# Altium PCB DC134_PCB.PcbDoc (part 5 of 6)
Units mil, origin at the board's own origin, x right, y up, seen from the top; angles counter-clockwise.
Board outline 4000 x 2750 mil, 6 copper layers (L1_Top Layer, L2_GND1, L3_Signal, L4_Plane, L5_GND2, L6_Bottom Layer), stack 57.7 mil thick; 399 components, 238 nets, 1523 pads, 671 vias.
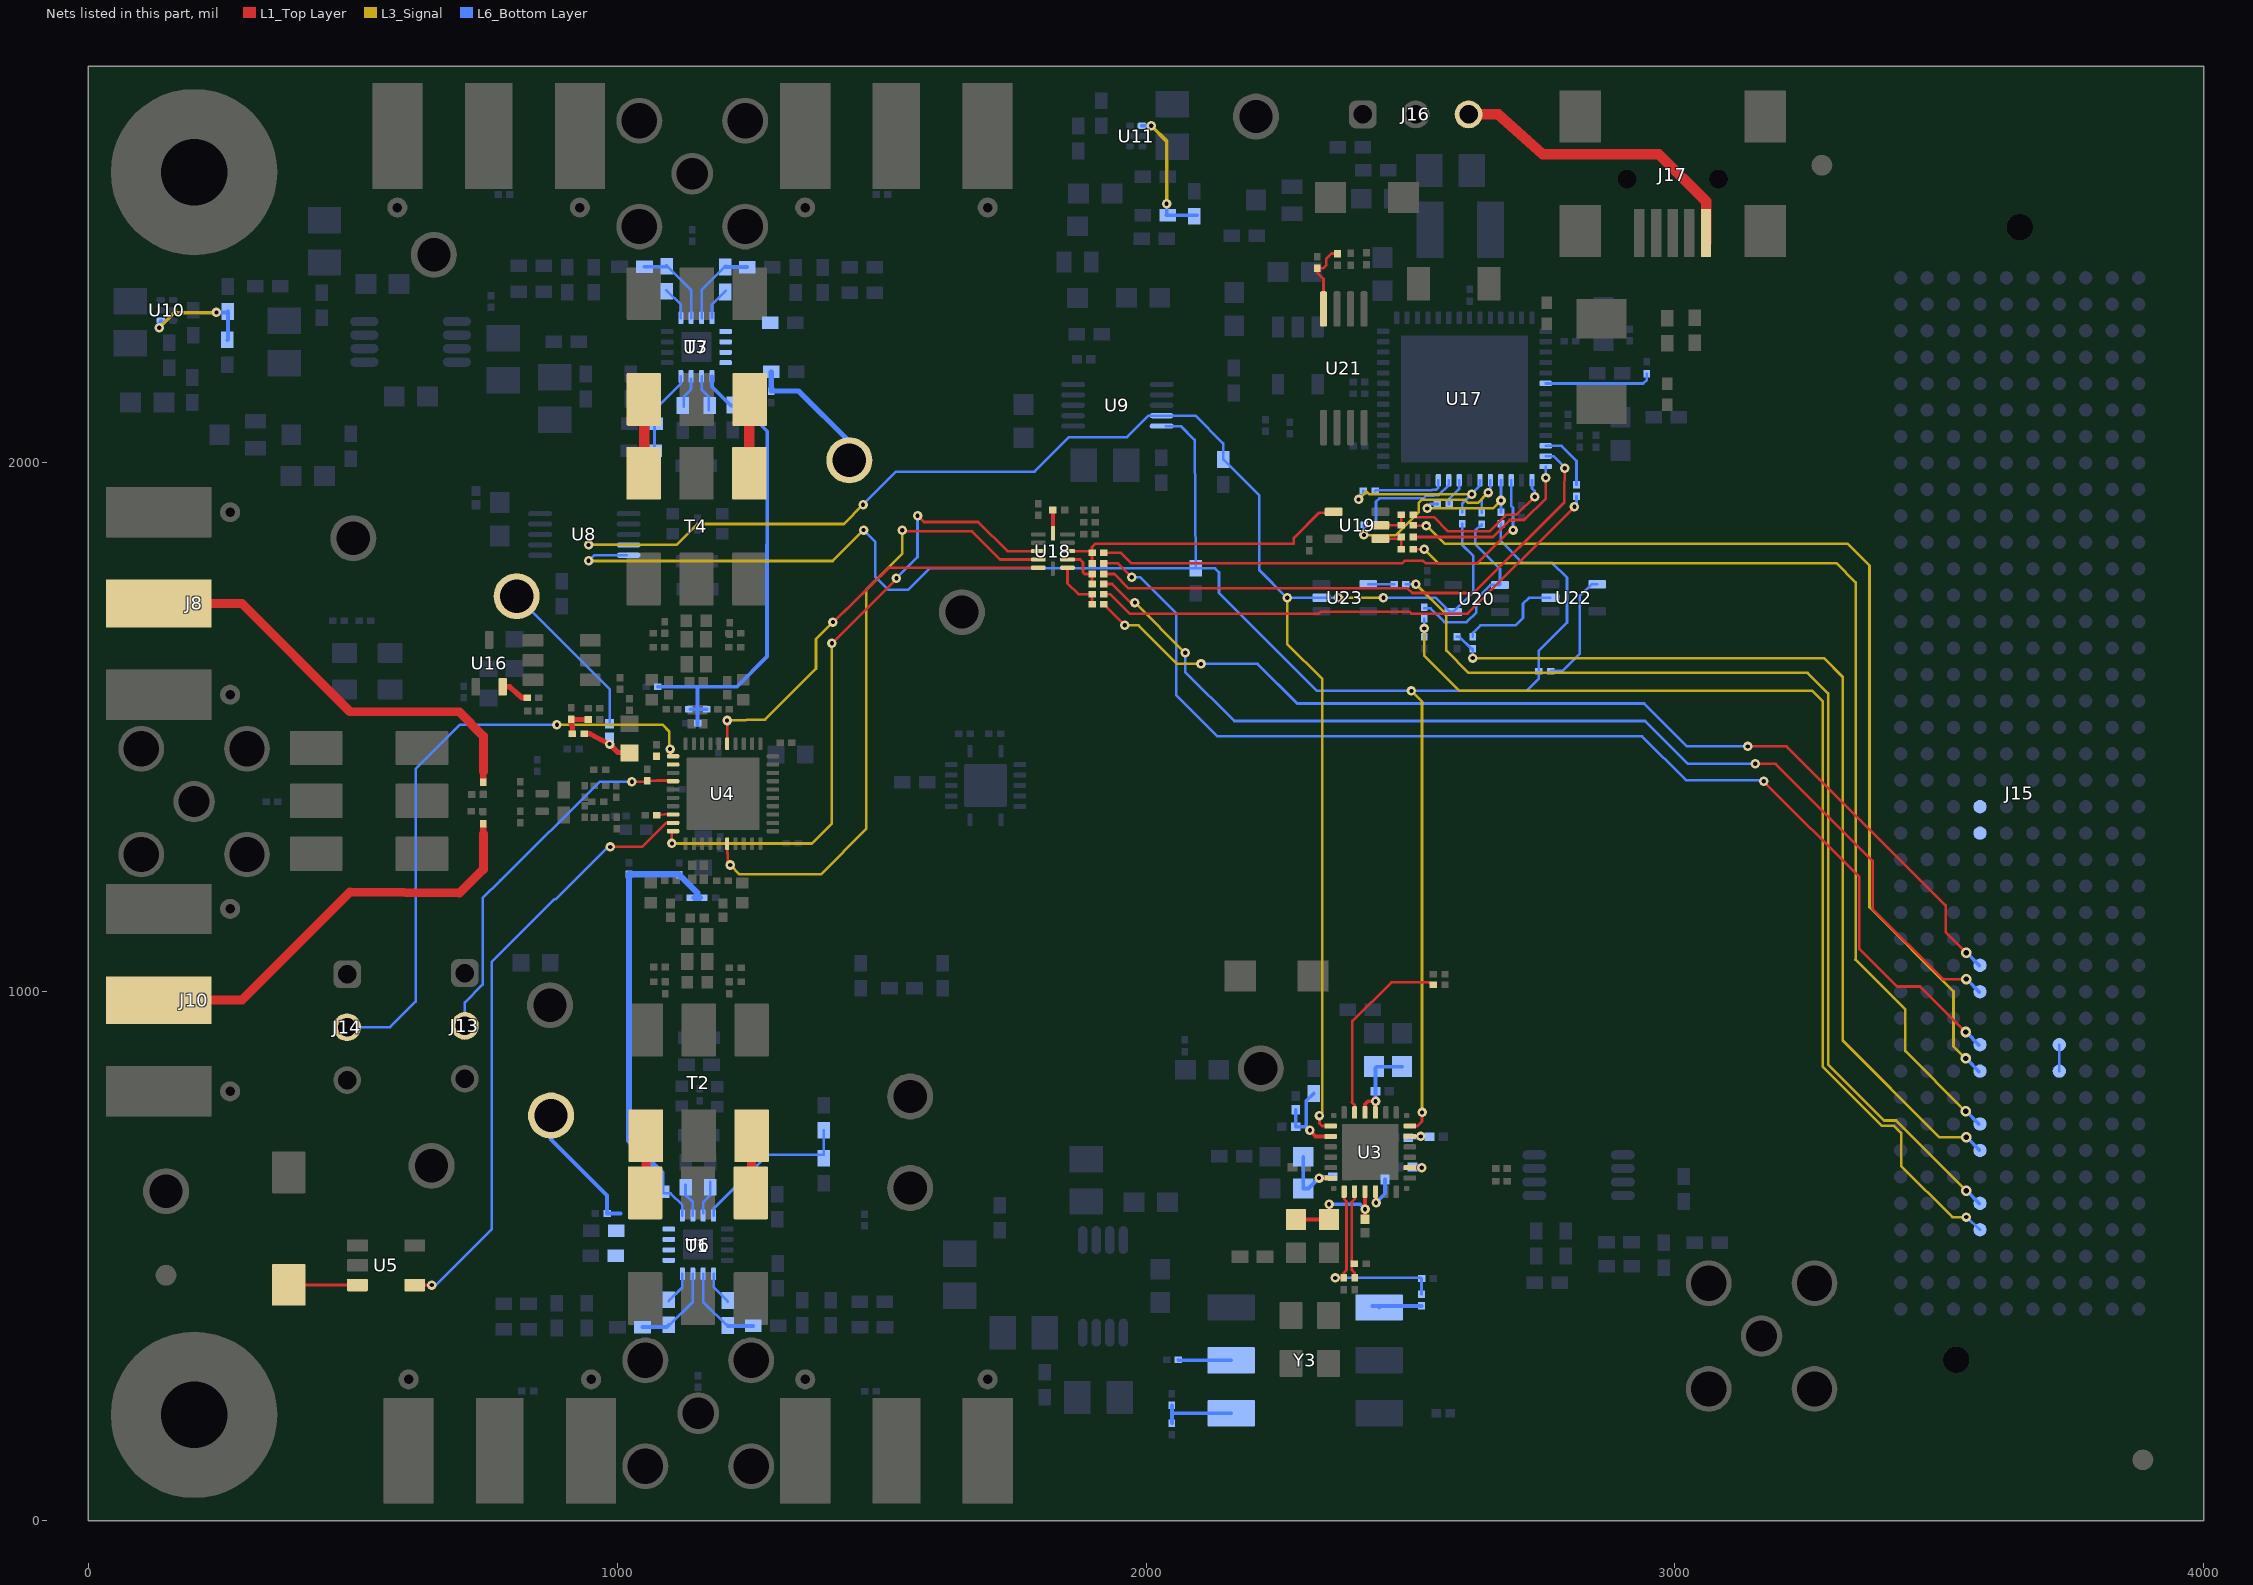
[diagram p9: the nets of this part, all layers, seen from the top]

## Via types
v1: diameter 18, hole 8, L1_Top Layer to L6_Bottom Layer, tented both sides, 429 vias
v2: diameter 20, hole 10, L1_Top Layer to L6_Bottom Layer, tented both sides, 183 vias
v3: diameter 19.68, hole 7.87, L1_Top Layer to L6_Bottom Layer, tented both sides, 37 vias
v4: diameter 19.68, hole 7.87, L1_Top Layer to L6_Bottom Layer, 17 vias
v5: diameter 18, hole 8, L1_Top Layer to L6_Bottom Layer, 5 vias

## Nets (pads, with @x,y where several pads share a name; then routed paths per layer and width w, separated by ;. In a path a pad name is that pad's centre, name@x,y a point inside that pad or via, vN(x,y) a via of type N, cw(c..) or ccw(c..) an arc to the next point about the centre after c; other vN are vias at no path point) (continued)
NetR62_1: R62.1 U3.17 | length 355.6
  L1_Top Layer w5: 2389.63,790.96 2394.47,786.11 U3.17@2394.47,771.8 ; 2390.13,790.96 2390.13,945 2464,1018 2534,1018 R62.1@2538.84,1013.66
NetR63_1: R63.1 Y3.4 | length 93.7
  L6_Bottom Layer w7: Y3.4@2428,405.98 R63.1@2520.87,405.98 ; Y3.4@2440.38,403.58 Y3.4@2440.96,403
NetR64_1: R64.1 R67.2 Y3.1 | length 146.4
  L6_Bottom Layer w7: R67.2@2049,184.02 2049,204 ; R64.1@2049,217.98 2049,204 ; Y3.1@2161.04,203 2050,203 2049,204
NetR66_1: R66.1 Y3.2 | length 100.4
  L6_Bottom Layer w7: R66.1@2061.02,304 2062.02,303 Y3.2@2161.04,303
NetR69_2: R69.2 U3.8 | length 40.6
  L1_Top Layer w7: U3.8@2498.8,667.47 v1(2521.47,667.47)
  L6_Bottom Layer w7: R69.2@2503.99,668.47 2520.47,668.47 v1(2521.47,667.47)
NetR77_1: R77.1 TP8.1 | length 313.8
  L6_Bottom Layer w5: TP8.1@810,1748 985.71,1572.29 R77.1@985.71,1506.99
NetR78_1: R78.1 R84.2 U6.2 | length 167.5
  L6_Bottom Layer w5: U6.2@1162.63,466.74 1162.63,413.81 R78.1@1209.32,367.12
  L6_Bottom Layer w7: R78.1@1209.32,369.12 1210.32,368.12 R84.2@1257.44,368.12
NetR78_2: R78.2 U6.1 | length 63.6
  L6_Bottom Layer w5: U6.1@1182.32,466.74 1182.32,441.37 R78.2@1209.32,414.37
NetR82_1: R82.1 U6.11 | length 63.8
  L6_Bottom Layer w5: 1162.63,601.74 1176.26,615.37 R82.1@1176.26,640.51 ; U6.11@1162.89,581.74 1162.89,601.12
NetR86_2: R86.2 R94.1 U6.3 | length 169
  L6_Bottom Layer w5: R94.1@1097.32,368.12 1142.95,413.75 U6.3@1142.95,466.74
  L6_Bottom Layer w7: R86.2@1047.86,366 1093.55,366 R94.1@1097.67,370.12
NetR88_1: R88.1 U6.10 | length 63.8
  L6_Bottom Layer w5: R88.1@1129.32,635.12 1129.32,615.74 1142.95,602.11 U6.10@1142.95,576.98
NetR94_2: R94.2 U6.4 | length 62.1
  L6_Bottom Layer w5: R94.2@1097.32,415.37 1123.26,441.31 U6.4@1123.26,466.74
NetR95_1: R95.1 R101.2 U7.2 | length 160.9
  L6_Bottom Layer w5: R95.1@1093.32,2373.74 1140,2327.06 U7.2@1140,2274.12
  L6_Bottom Layer w7: R101.2@1051.62,2371 1092.7,2371 R95.1@1093.32,2371.62
NetR95_2: R95.2 U7.1 | length 63.6
  L6_Bottom Layer w5: R95.2@1093.32,2326.5 1120.32,2299.5 U7.1@1120.32,2274.12
NetR99_1: R99.1 U7.11 | length 58
  L6_Bottom Layer w5: R99.1@1126,2106 1126,2125.38 ; 1126.37,2125.49 1140,2139.12 ; 1139.74,2139.74 U7.11@1139.74,2159.12
NetR103_2: R103.2 R111.1 U7.3 | length 159.5
  L6_Bottom Layer w5: U7.3@1159.69,2274.12 1159.69,2327.11 R111.1@1205.32,2372.74
  L6_Bottom Layer w7: R111.1@1204,2370.62 1204.12,2370.5 R103.2@1245.88,2370.5
NetR105_1: R105.1 U7.10 | length 69.5
  L6_Bottom Layer w5: U7.10@1159.69,2163.88 1159.69,2138.75 1173.32,2125.12 ; R105.1@1173,2100 1173,2125.13
NetR111_2: R111.2 U7.4 | length 62.1
  L6_Bottom Layer w5: U7.4@1179.37,2274.12 1179.37,2299.55 R111.2@1205.32,2325.5
NetR119_1: R119.1 R121.2 U10.1 | length 211.7
  L3_Signal w7: v1(134,2255.5) 162.5,2284 v1(242.38,2284.5)
  L6_Bottom Layer w7: v1(134,2255.5) 134,2265.28 U10.1@137.67,2268.95 ; v1(242.38,2284.5) 262.12,2284.5 R119.1@264,2286.38 264,2233.62 R121.2@263,2232.62
NetR120_1: R120.1 R122.2 U11.1 | length 257.6
  L3_Signal w7: v1(2009.81,2637.77) 2039,2608.59 v1(2039,2490.09)
  L6_Bottom Layer w7: U11.1@1992.33,2637.77 v1(2009.81,2637.77) ; v1(2039,2490.09) 2039,2468.83 2038.25,2468.09 R120.1@2041.13,2468.09 R122.2@2096.25,2468.09
NetR128_2: R128.2 R129.2 R130.1 | length 59.8
  L1_Top Layer w10: R130.1@915.48,1487.98 915.48,1502 913.5,1503.98 R129.2@913.5,1514.95 R128.2@945.48,1514.95
NetR131_1: R131.1 U16.2 | length 54.3
  L1_Top Layer w10: U16.2@783.59,1576.71 797,1576.71 819.98,1556.02 R131.1@829.98,1556.02
NetR133_2: R133.2 R139.2 U18.7 | length 103.2
  L1_Top Layer w5: U18.7@1851.56,1801.8 1851.56,1772.44 1872,1752 R139.2@1897.98,1752 R133.2@1897.98,1733
NetR134_2: R134.2 R140.2 U18.8 | length 88
  L1_Top Layer w5: U18.8@1851.56,1817.54 1875.46,1817.54 1881,1812 1881,1793 1884,1790 R140.2@1897.98,1790 R134.2@1897.98,1771
NetR135_2: R135.2 R141.2 U19.1 | length 57.9
  L1_Top Layer w5: U19.1@2443.29,1856.41 2482.39,1856.41 R135.2@2482.39,1837.59
NetR136_2: R136.2 R142.2 U19.2 | length 59.7
  L1_Top Layer w5: U19.2@2443.29,1882 R136.2@2482.98,1882 R142.2@2482.98,1902
NetR137_2: R137.2 R144.2 U18.9 U19.4 | length 569.7
  L1_Top Layer w5: U18.9@1851.56,1833.29 1894.69,1833.29 R144.2@1897.98,1830 ; R137.2@1897.98,1810 R144.2@1897.98,1830 ; U19.4@2354.71,1907.59 2352.71,1905.59 2326.67,1905.59 2279.41,1858.33 2279.41,1847 1904,1847 1897.98,1840.98 R144.2@1897.98,1830
NetR138_1: R138.1 U17.12 | length 115.2
  L6_Bottom Layer w5: U17.12@2755.56,2032.42 2785.58,2032.42 2814,2004 R138.1@2814,1959.02
NetR138_2: R138.2 R139.1 | length 1013.5
  L1_Top Layer w5: R139.1@1920.02,1752 1932,1752 1969,1715 2326.67,1715 2330.17,1718.5 2498.52,1718.5 2502.02,1715 2608,1715 v1(2810,1917)
  L6_Bottom Layer w5: v1(2810,1917) 2814,1921 R138.2@2814,1936.98
NetR140_1: R140.1 U17.13 | length 1067.7
  L1_Top Layer w5: R140.1@1920.02,1790 1940,1790 1967,1763 2494.67,1763 2503.55,1754.11 2619.45,1754.11 2791,1925.67 2791,1942 v1(2792,1990)
  L6_Bottom Layer w5: U17.13@2755.56,2012.73 2770.27,2012.73 2792,1991 v1(2792,1990)
NetR141_1: R141.1 U17.14 | length 341.2
  L1_Top Layer w5: R141.1@2505.02,1860 2656,1860 2688,1892 2693.67,1892 ; 2693.76,1892 2715,1892 2756,1933 v1(2756,1972)
  L6_Bottom Layer w5: U17.14@2755.56,1993.05 2755.56,1986.44 v1(2756,1972)
NetR142_1: R142.1 U17.15 | length 303.4
  L1_Top Layer w5: R142.1@2505.02,1902 2509.52,1897.5 2544.5,1897.5 2571.46,1870.54 2649.57,1870.54 2681.02,1902 2700,1902 v1(2735,1936)
  L6_Bottom Layer w5: U17.15@2730,1967.43 2730,1952 2735,1947 v1(2735,1936)
NetR143_1: R143.1 U17.22 | length 53.8
  L6_Bottom Layer w5: R143.1@2573.02,1921.57 2573.02,1931.53 2592.18,1950.69 U17.22@2592.18,1967.46
NetR143_2: R143.2 R156.1 U17.18 | length 245.4
  L3_Signal w5: v1(2532,1914) 2656.29,1914 v1(2671.29,1929)
  L6_Bottom Layer w5: v1(2532,1914) 2532,1917 v1@2536.57,1921.57 ; R143.2@2550.97,1921.57 v1@2536.57,1921.57 ; R143.2@2551.66,1922.34 2537.34,1922.34 v1@2536.57,1921.57 ; U17.18@2670.92,1967.46 2671.29,1967.08 R156.1@2671.29,1907.02
NetR144_1: R144.1 U17.17 | length 909.8
  L1_Top Layer w5: R144.1@1920.02,1830 1953,1830 1973,1810 2484,1810 2489,1815 2524,1815 2529,1810 2626,1810 2690.78,1874.78 2692.56,1873 v1(2694,1873)
  L6_Bottom Layer w5: U17.17@2690.6,1967.46 2690.6,1919 2694,1915.6 v1(2694,1873)
NetR146_1: R146.1 U17.23 | length 203.5
  L6_Bottom Layer w5: R146.1@2435.02,1883 2435.02,1927 2441.22,1933.2 2524.87,1933.2 2529.81,1938.15 2544.14,1938.15 2545.49,1939.5 2553.5,1939.5 2572.49,1958.49 U17.23@2572.49,1967.46
NetR146_2: R146.2 R157.1 U17.19 | length 372.2
  L3_Signal w5: v1(2412,1864) 2412,1863 2472,1863 2515.5,1906.5 2515.5,1923.83 2522.17,1930.5 2603.17,1930.5 2609.17,1924.5 2627.5,1924.5 v1(2647,1944)
  L6_Bottom Layer w5: v1(2412,1864) 2412,1882.02 R146.2@2412.98,1883 ; R157.1@2635,1906.02 2635,1932 v1(2647,1944) 2651.23,1948.23 U17.19@2651.23,1967.46
NetR147_1: R147.1 U18.12 | length 44.2
  L1_Top Layer w7: U18.12@1824,1866.76 R147.1@1823.98,1911
NetR149_1: R149.1 U17.24 | length 136.5
  L6_Bottom Layer w5: R149.1@2433.02,1947 2434.17,1948.15 2539.99,1948.15 2541.35,1949.5 2548.84,1949.5 2552.8,1953.46 U17.24@2552.8,1967.46
NetR149_2: R149.2 R161.1 U17.20 | length 316.3
  L3_Signal w5: v1(2402,1931) 2417,1946 2422,1941 v1(2616,1941)
  L6_Bottom Layer w5: v1(2402,1931) 2410.98,1939.98 R149.2@2410.98,1947 ; R161.1@2598,1907.02 2598,1923.55 2631.55,1957.09 U17.20@2631.55,1967.46
NetR152_2: R152.2 U17.6 | length 206.6
  L6_Bottom Layer w5: U17.6@2755.56,2150.53 2755.56,2150.19 2940.17,2150.19 2947,2157.02 R152.2@2947,2168.98
NetR157_2: R157.2 R167.2 U20.1 | length 339
  L6_Bottom Layer w5: R167.2@2526,1725.02 2537.98,1725.02 2564,1699 2606.08,1699 2624.5,1717.42 2624.5,1742.5 2651.21,1769.21 U20.1@2669.4,1769.21 2669.4,1799.6 2622.5,1846.5 2622.5,1871.83 2632.17,1881.5 2635,1881.5 R157.2@2635,1883.98
NetR160_1: R160.1 R162.1 U21.4 | length 138.5
  L1_Top Layer w5: U21.4@2335.61,2291.2 2335.61,2348 2324,2359.61 R160.1@2324,2367.98 2334.98,2367.98 2340.59,2373.59 2340.59,2386 2350.64,2396.05 R162.1@2362,2396.02
NetR165_2: R165.2 U22.2 | length 197.6
  L6_Bottom Layer w5: R165.2@2618,1671.02 2618,1678.65 2632.35,1693 2699,1693 2713,1707 2713,1734 2724,1745 U22.2@2764.71,1745
NetR166_1: R166.1 U22.4 | length 220.3
  L6_Bottom Layer w5: R166.1@2765.02,1606 2766.02,1607 2788,1607 2820,1639 2820,1748 2842.59,1770.59 U22.4@2853.29,1770.59
NetR168_2: R168.2 U23.4 | length 48.7
  L6_Bottom Layer w5: U23.4@2420.29,1770.61 R168.2@2468.98,1770.61
NetS1_2: S1.2 U5.3 | length 129.6
  L1_Top Layer w5: S1.2@379.25,445.45 U5.3@508.87,445.45
NetT1_4: T1.4 T2.6 | length 122
  L1_Top Layer w17: T1.4@1254.24,605.74 T2.6@1254.24,727.74
NetT1_6: T1.6 T2.4 | length 122
  L1_Top Layer w17: T1.6@1054.24,605.74 T2.4@1054.24,727.74
NetT3_4: T3.4 T4.6 | length 110
  L1_Top Layer w20: T4.6@1051,1984 T3.4@1051,2094
NetT3_6: T3.6 T4.4 | length 110
  L1_Top Layer w20: T4.4@1249.98,1983 T3.6@1249.98,2093
OE: R70.1 R72.2 U3.11 | length 45.2
  L1_Top Layer w7: U3.11@2498.8,726.53 v1(2519.47,726.53)
  L6_Bottom Layer w7: R72.2@2495.99,724 2516.94,724 v1(2519.47,726.53)
PD_AMP_CHA: R83.1 R87.2 U6.12 | length 309.3
  L6_Bottom Layer w5: U6.12@1182.32,576.98 1182.32,589.74 1283.87,691.74 1390.25,691.74 1390.87,692.37 R87.2@1390.87,737.74
PD_AMP_CHB: R100.1 R104.2 U7.12 | length 160.2
  L6_Bottom Layer w5: R100.1@1070.52,2024 R104.2@1070.52,2074 1071,2074.48 1071,2100 1120.32,2150.32 U7.12@1120.32,2163.88
PDN_SYNC: J14.2 U4.1 | length 1157.3
  L1_Top Layer w5: U4.1@1100,1444.72 v1(1100,1459)
  L3_Signal w5: v1(886,1505) 1086,1505 1098.5,1492.5 1098.5,1460.5 v1(1100,1459)
  L6_Bottom Layer w5: J14.2@489.5,933 570.5,933 619,981.5 619,1421.5 702.5,1505 v1(886,1505)
PDN_SYNC_FPGA: J15.G21
REFBUF: C46.1 J13.2 U4.4 | length 707.7
  L1_Top Layer w5: v1(1028,1397) 1055.02,1397 C46.1@1057,1398.98 1075.14,1398.98 1075.67,1399.5 1104.63,1399.5 U4.4@1105.51,1398.62 ; U4.4@1103.54,1398.62 U4.4@1103.54,1398.84
  L6_Bottom Layer w5: J13.2@712,935.5 712,980.08 745.75,1013.83 745.75,1177.28 779.24,1210.77 967,1397 v1(1028,1397)
REFSEL: R61.2 U3.4 | length 72.1
  L1_Top Layer w7: U3.4@2433.84,622.2 2435,621.04 v1(2435,601.3)
  L6_Bottom Layer w7: v1(2435,601.3) 2452,618.3 R61.2@2452,645.01
RESET: U4.9 U5.4 | length 1147
  L1_Top Layer w5: U5.4@617.13,445.45 v1(649.55,445.45) ; v1(987,1274) 1047,1274 1092.88,1319.88 U4.9@1105.51,1319.88
  L6_Bottom Layer w5: v1(649.55,445.45) 657.45,445.45 763,551 763,1057 881.17,1175.17 884.17,1175.17 983,1274 v1(987,1274)
RESET_FPGA: J15.G22
SCL_I2C: R154.1 R156.2 R166.2 U3.12 U8.5 U9.5 | length 3684.4
  L1_Top Layer w5: U3.12@2498.8,746.21 2513.21,746.21 2522,755 v1(2522,772)
  L3_Signal w5: v1@946.41,1814.59 1407.59,1814.59 v1(1466,1873) ; v1(2502,1569) 2522,1549 v1(2522,772)
  L6_Bottom Layer w5: v1(946,1815) 956.71,1825.71 U8.5@1017.66,1825.71 ; v1(1466,1873) 1488,1851 1488,1785 1513,1760 1550,1760 1590.62,1800.62 R154.1@2094,1800.62 ; U9.5@2037.16,2069.63 2065.7,2069.63 2091.91,2043.42 2091.91,2040 R154.1@2094,1800.62 ; R156.2@2671.29,1884.98 2670.92,1884.6 2670.92,1852 2711.92,1811 2768,1811 2796,1783 2796,1698 2742.98,1644.98 2742.98,1592.6 2719.38,1569 v1(2502,1569) 2323,1569 2138,1754 2138,1793 2130.38,1800.62 R154.1@2094,1800.62
SCL_I2C_FPGA: J15.G34 R163.2 R165.1 | length 1802.9
  L3_Signal w5: v1(2618,1631) 3282,1631 3317.5,1595.5 3317.5,907.5 3499.85,725.15 v2(3551,725.15)
  L6_Bottom Layer w5: R163.2@2588,1671.02 2592.98,1671.02 2615.02,1648.98 R165.1@2618,1648.98 v1(2618,1631)
  L6_Bottom Layer w6.6: v2@3552,725.15 J15.G34@3576,700.3
SCLK: U4.35 U18.5 | length 785.1
  L1_Top Layer w5: U4.35@1207.87,1469.49 v1@1207.87,1515 ; v1(1408,1699) v1@1408.89,1699 ; v1@1409,1699 v1@1408.89,1699 ; U18.5@1796.44,1801.8 1514.2,1801.8 1408.94,1699.06 v1@1408.89,1699
  L3_Signal w5: v1(1207.87,1513) 1280,1515 1376,1611 1376,1667 v1(1408,1699)
SCLK_FPGA: J15.G27 R133.1 | length 1967.9
  L1_Top Layer w5: R133.1@1920.02,1733 v1(1960.02,1693) ; v1(3138,1464) 3211.18,1464 3512,1163.18 3512,1113 v2(3551,1074)
  L3_Signal w5: v1(1960.02,1693) 1986,1693 2059,1620 v1(2104,1620)
  L6_Bottom Layer w5: v1(2104,1620) 2211,1620 2286,1545 2942,1545 3023,1464 v1(3138,1464)
  L6_Bottom Layer w6.6: v2@3552,1074 J15.G27@3576,1049.15
SDA_I2C: R155.1 R161.2 U3.19 U8.4 U9.4 U20.4 U23.2 | length 3300.6
  L1_Top Layer w5: v1(2328,766) 2328,751 2332.79,746.21 U3.19@2349.2,746.21
  L3_Signal w5: v1(946,1845) 1112,1845 1151.5,1884.5 1428.5,1884.5 v1(1465,1921) ; v1(2267,1745.02) 2267,1658 2333.5,1591.5 2333.5,771.5 v1(2328,766) ; v1(2363.98,1745.02) v1(2449.02,1745.02)
  L6_Bottom Layer w5: v1(946,1845) 946.39,1845.39 U8.4@1017.66,1845.39 ; v1(1465,1921) 1527.39,1983.39 1789.39,1983.39 1854.75,2048.75 1964.25,2048.75 2004.82,2089.31 2037.16,2089.31 2093.69,2089.31 2146,2037 R155.1@2146,2007 ; R155.1@2146,2006.62 R155.1@2146,2007 ; v1(2363.98,1745.02) U23.2@2331.71,1745.02 v1(2267,1745.02) 2214,1798.02 2214,1939 R155.1@2146,2007 ; v1(2449.02,1745.02) 2547.93,1745.02 2574.92,1718.03 U20.4@2580.82,1718.03 2619,1756.21 2619,1824 2598,1845 R161.2@2598,1884.98
SDA_IN_I2C_FPGA: J15.G36 R168.1 | length 2020.4
  L3_Signal w5: v1(2510.39,1770.61) 2568,1713 2568,1645 2610,1603 3251,1603 3290,1564 3290,862.25 3395.75,756.5 3418.5,756.5 v2(3551,624)
  L6_Bottom Layer w5: R168.1@2491.02,1770.61 v1(2510.39,1770.61)
  L6_Bottom Layer w6.6: v2@3552,624 J15.G36@3576,599.15
SDA_OUT_I2C_FPGA: J15.G37 R164.2 R167.1 | length 2026.3
  L3_Signal w5: v1(2526,1687) 2526,1636 2593,1569 3260,1569 3280,1549 3280,858.11 3391.61,746.5 3414.36,746.5 3428,732.86 3428,671 3525,574 v1(3551,574)
  L6_Bottom Layer w5: R164.2@2526,1671.02 v1(2526,1687) R167.1@2526,1705.09 ; v1(3551,574) J15.G37@3577,550
SDIO: U4.10 U18.3 | length 1247.9
  L1_Top Layer w5: v1(1103.54,1280.46) 1103.54,1302.17 U4.10@1105.51,1304.13 ; v1(1406,1659) 1528,1781 v1(1528,1782) ; v1(1568,1900.15) 1579.85,1888.29 1682.71,1888.29 1737.71,1833.29 U18.3@1796.44,1833.29
  L3_Signal w5: v1(1103.54,1280.46) 1368.46,1280.46 1406,1318 v1(1406,1659)
  L6_Bottom Layer w5: v1(1528,1782) 1568,1822 v1(1568,1900.15)
SDIO_I_FPGA: J15.G31 R136.1 | length 1936.4
  L1_Top Layer w5: R136.1@2505.02,1882 2506.02,1881 v1(2530,1881)
  L3_Signal w5: v1(2530,1881) 2531,1881 2565.04,1846.96 3071.93,1846.96 3071.97,1847 3327,1847 3368,1806 3368,1160 3527,1001 3527,897 v2(3550,874)
  L6_Bottom Layer w6.6: v2@3551,874 J15.G31@3575,849.15
SDIO_O_FPGA: J15.G30 R137.1 | length 2203.2
  L1_Top Layer w5: R137.1@1920.02,1810 1946.98,1810 v1(1972.98,1784) ; v1(3168,1398) 3349,1217 3349,1081 3420,1010 3464,1010 v2(3550,924)
  L6_Bottom Layer w5: v1(1972.98,1784) 1989,1784 2057,1716 2057,1561 2135,1483 2938,1483 3020.85,1400.15 3168,1400.15 v1(3168,1398)
  L6_Bottom Layer w6.6: v2@3551,924 J15.G30@3575,899.15
SDIO_OE_FPGA: J15.G33 R135.1 | length 1984.1
  L1_Top Layer w5: R135.1@2505.02,1837 v1(2526,1837)
  L3_Signal w5: v1(2526,1837) 2552.34,1810.66 3305.34,1810.66 3342,1774 3342,1061 3341.66,1060.66 3436,966.31 3436,888 v2(3550,774)
  L6_Bottom Layer w6.6: v2@3551,774 J15.G33@3575,749.15
SECREF_N: R59.1 R68.1 U3.2 | length 167.5
  L1_Top Layer w5: R59.1@2394.47,459.02 2394.47,468.61 2389.24,473.85 2389.24,602.65 2394.47,607.89 U3.2@2394.47,622.2
SECREF_P: R55.1 R63.2 R65.2 U3.1 | length 376.8
  L1_Top Layer w5: v1(2357.65,459.02) R55.1@2374,459.02 2374,468.61 2379.24,473.85 2379.24,603.44 2374.79,607.89 U3.1@2374.79,622.2
  L6_Bottom Layer w5: v1(2357.65,459.02) 2519.25,459.02 2520.87,457.4 R63.2@2520.87,428.02
SEN: U4.16 U18.4 | length 1215.6
  L1_Top Layer w5: U4.16@1207.99,1280.06 1207.99,1262.46 1209.06,1261.39 1209.06,1244.7 v1(1214,1239.76) ; v1(1539,1872.54) 1541,1870.54 1671,1870.54 1724,1817.54 U18.4@1796.44,1817.54
  L3_Signal w5: v1(1214,1239.76) 1231.7,1222.06 1385.06,1222.06 1471,1308 1471,1760 1539,1828 v1(1539,1872.54)
SEN_FPGA: J15.G28 R134.1 | length 2049
  L1_Top Layer w5: R134.1@1920.02,1771 1936,1771 1971,1736 v1(1979,1736) ; v1(3152,1431) 3190.41,1431 3374,1247.41 3374,1157 3507,1024 v2(3551,1024)
  L3_Signal w5: v1(1979,1736) v1(2074,1641)
  L6_Bottom Layer w5: v1(2074,1641) 2074,1605 2167,1512 2944,1512 3025,1431 v1(3152,1431)
  L6_Bottom Layer w6.6: v2@3552,1024 J15.G28@3576,999.15
SMA_CLK_N: J10.1 R49.1 | length 833.3
  L1_Top Layer w12: 747.02,1298.18 R49.1@747.02,1318.94
  L1_Top Layer w17: J10.1@105,984.25 J10.1@133,984.25 290.36,984.25 494.61,1188.5 702,1187.15 747.02,1232.18 ; 747.02,1230.9 747.02,1232.18 ; 747.02,1298.18 747.02,1232.18
SMA_CLK_P: J8.1 R43.1 | length 833.3
  L1_Top Layer w12: R43.1@747.02,1395.59 747.02,1416.35
  L1_Top Layer w17: J8.1@105,1734.25 J8.1@133,1734.25 290.36,1734.25 494.61,1530 702,1528.65 747.02,1483.63 747.02,1416.35
STATUS: R54.1 R57.2 R58.2 U3.20 | length 164.8
  L1_Top Layer w7: v1(2310,738) 2320.47,726.53 U3.20@2349.2,726.53
  L6_Bottom Layer w7: R54.1@2283,777.01 R57.2@2282.99,745 2303,745 2303,793.76 R58.2@2317,807.76
TDI_TDO: J15.D30 J15.D31 | length 50
  L6_Bottom Layer w5: J15.D31@3727,850 J15.D30@3727,900
USB_+5Vin: J16.3 J17.1 | length 592.8
  L1_Top Layer w20: J16.3@2610,2659 2666,2659 2750,2584 2969.91,2584 3058.99,2494.91 J17.1@3058.99,2434.64 J17.1@3058.99,2416.64
VCM: R73.2 U4.8 | length 26.7
  L1_Top Layer w5: R73.2@1076.87,1333.62 1089.75,1335.5 U4.8@1103.41,1335.5
VCM_FDA_CHA: C5.2 C51.2 R7.1 R8.2 R74.2 U6.9 | length 856.5
  L6_Bottom Layer w5: C51.2@1084.49,622.9 1089.31,618.74 1101.32,618.74 1123.26,596.8 U6.9@1123.26,576.98
  L6_Bottom Layer w12: C51.2@1083.49,621.74 1083.49,658 1022.5,718.99 R74.2@1022.5,1221.98 1116.78,1221.98 C5.2@1117.28,1221.48 1151.42,1187.33 1151.42,1178.08 ; 1146.8,1178.08 1156.05,1178.08
VCM_FDA_CHB: C13.2 C56.2 R21.1 R22.2 R75.2 U7.9 | length 910.8
  L6_Bottom Layer w7: R75.2@1077.02,1576.98 1147.5,1576.98 1226.48,1576.98 1283.5,1634 1284,2060 1234.38,2109.62 1228.76,2109.62 1229.76,2108.62 1214.81,2108.62 1179.37,2144.06 U7.9@1179.37,2163.88 ; R21.1@1138.82,1534.5 1150.5,1534.5 ; C13.2@1152,1504.52 1152,1572.48 ; 1156,1534.5 R22.2@1169.02,1534.5
VDD_REF: C28.1 C29.1 L8.2 U3.3 | length 215.2
  L1_Top Layer w7: L8.2@2283.89,569.5 C28.1@2346.26,569.5 v1(2346.26,598.26) ; C29.1@2414.16,569.99 v1(2414.16,588.68) U3.3@2414.16,622.2
  L6_Bottom Layer w7: v1(2346.26,598.26) 2404.57,598.26 v1(2414.16,588.68)
VDD_VCO: C32.1 C33.1 L9.2 U3.24 | length 147.2
  L1_Top Layer w7: v1(2327.21,647.79) U3.24@2349.2,647.79
  L6_Bottom Layer w7: L9.2@2297.44,688 C32.1@2297.44,628 2307.43,628 v1(2327.21,647.79) 2329.57,650.15 C33.1@2353.51,650.15
VDDO_12: C35.1 C36.1 L10.2 U3.15 U3.16 | length 173.1
  L1_Top Layer w7: U3.16@2414.16,771.8 2414.16,787.16 2420.01,793.01 v1(2434.01,793.01) 2434.01,771.97 U3.15@2433.84,771.8
  L6_Bottom Layer w7: v1(2434.01,793.01) C36.1@2434.01,811.75 2434.01,855.7 2436.81,858.5 C35.1@2484.32,858.5
VREF: C44.1 C45.1 R77.2 R130.2 U4.2 | length 98.9
  L1_Top Layer w10: R130.2@937.52,1487.98 948.02,1487.98 v1(985.71,1468.29) 1001.56,1452.44 C44.1@1025,1452.44
VS+_CHA: C66.1 C67.1 R91.1 TP9.1 U6.5 U6.6 U6.7 U6.8 | length 255.1
  L6_Bottom Layer w7: TP9.1@875,766 875,720.61 980.89,614.72 R91.1@980.89,580.74 1006.87,580.74
VS+_CHB: C64.1 C65.1 R106.1 TP11.1 U7.5 U7.6 U7.7 U7.8 | length 223.3
  L6_Bottom Layer w10: R106.1@1291.38,2136.02 1342.98,2136.02 TP11.1@1439,2040 ; R106.1@1291.38,2136.14 C65.1@1291.38,2172
pads on no net: FID1.1 FID2.1 FID3.1 H1.1 H2.1 H3.0 H4.0 J15.A2 J15.A3 J15.A6 J15.A7 J15.A10 J15.A11 J15.A14 J15.A15 J15.A18 J15.A19 J15.A22 J15.A23 J15.A26 J15.A27 J15.A30 J15.A31 J15.A34 J15.A35 J15.A38 J15.A39 J15.B1 J15.B4 J15.B5 J15.B8 J15.B9 J15.B12 J15.B13 J15.B16 J15.B17 J15.B20 J15.B21 J15.B24 J15.B25 J15.B28 J15.B29 J15.B32 J15.B33 J15.B36 J15.B37 J15.B40 J15.C2 J15.C3 J15.C6 J15.C7 J15.C10 J15.C11 J15.C14 J15.C15 J15.C18 J15.C19 J15.C22 J15.C23 J15.C26 J15.C27 J15.C30 J15.C31 J15.C34 J15.C35 J15.C37 J15.C39 J15.D1 J15.D4 J15.D5 J15.D8 J15.D9 J15.D11 J15.D12 J15.D14 J15.D15 J15.D17 J15.D18 J15.D20 J15.D21 J15.D23 J15.D24 J15.D26 J15.D27 J15.D29 J15.D32 J15.D33 J15.D34 J15.D35 J15.D36 J15.D38 J15.D40 J15.E18 J15.E19 J15.E21 J15.E22 J15.E24 J15.E25 J15.E27 J15.E28 J15.E30 J15.E31 J15.E33 J15.E34 J15.E36 J15.E37 J15.E39 J15.F1 J15.F7 J15.F8 J15.F10 J15.F11 J15.F13 J15.F14 J15.F16 J15.F17 J15.F19 J15.F20 J15.F22 J15.F23 J15.F25 J15.F26 J15.F28 J15.F29 J15.F31 J15.F32 J15.F34 J15.F35 J15.F37 J15.F38 J15.F40 J15.G2 J15.G3 J15.G7 J15.G9 J15.G10 J15.G12 J15.G13 J15.G15 J15.G16 J15.G18 J15.G19 J15.G24 J15.G25 J15.H1 J15.H5 J15.H7 J15.H8 J15.H10 J15.H11 J15.H13 J15.H14 J15.H16 J15.H17 J15.H19 J15.H20 J15.H22 J15.H23 J15.H25 J15.H26 J15.H28 J15.H29 J15.H31 J15.H32 J15.H34 J15.H35 J15.H37 J15.H38 J15.H40 J15.J2 J15.J3 J15.J6 J15.J7 J15.J9 J15.J10 J15.J12 J15.J13 J15.J15 J15.J16 J15.J18 J15.J19 J15.J21 J15.J22 J15.J24 J15.J25 J15.J27 J15.J28 J15.J30 J15.J31 J15.J33 J15.J34 J15.J36 J15.J37 J15.J39 J15.K1 J15.K4 J15.K5 J15.K7 J15.K8 J15.K10 J15.K11 J15.K13 J15.K14 J15.K19 J15.K20 J15.K22 J15.K23 J15.K25 J15.K26 J15.K28 J15.K29 J15.K31 J15.K32 J15.K34 J15.K35 J15.K37 J15.K38 J15.K40 J15.MH1 J15.MH2 J17.4 J17.10 J17.11 LBL1.0 T1.2 T2.2 T3.2 T4.2 T5.2 U1.1 U1.4 U2.6 U3.7 U3.9 U3.10 U3.13 U3.14 U3.A1 U3.A2 U3.A3 U3.A4 U4.27 U6.17@1152.79,521.86 U7.17@1149.84,2219 U8.3 U9.3 U14.4 U17. U17.25 U17.26 U17.27 U17.28 U17.29 U17.30 U17.32 U17.33 U17.34 U17.35 U17.37 U17.38 U17.39 U17.40 U17.42 U17.46 U17.47 U17.48 U17.49 U17.51 U17.52 U17.53 U17.54 U18.2 U18.10 U21.6 U21.7 Y3.5
copper on no net: | length 106.6
  L1_Top Layer w5: 419,1357 v1(484,1357)
  L4_Plane w4.4: 3403,1575 3403,1582
  L6_Bottom Layer w6.6: v2@3553,2074.26 3576.7,2049.71 3577,2049.4
  other v2: 3552,2074.26

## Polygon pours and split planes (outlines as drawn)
GND on L2_GND1 "L2_GND1_GND_P046" (solid, remove dead copper, pour order 46): 20,2730 1120,2730 3980,2730 3980,20 1834.59,20 20,20 20,1462
+3.3V on L4_Plane "L4_PLANE_+3.3V_P124" (solid, remove dead copper, pour order 124): 2166,2730 2170,2734 3371,2734 3371,0 1840,0 889,0 889,704 1840,704 1837.4,2157 1489,2157 1489,1991 1123.91,1991 1123.91,2105.37 1054,2105.37 1054,2157 349.77,2157 349.22,2395.52 1840,2394.49 1839,2395.49 2166,2395.49
+5V on L4_Plane "L4_PLANE_+5V_P122" (solid, remove dead copper, pour order 122): 2192,2409 983,2409 633.5,2404.73 462,2404.73 462,2346.25 305.25,2346.25 363.73,2404.73 402.5,2443.5 402.5,2742 2192,2742
GND on L4_Plane "L4_PLANE_GND_P116" (solid, remove dead copper, pour order 116): 3381,683 3381,12.51 3980,12.51 3980,2395.51 3980,2722.51 3381,2722.51
IOVDD on L4_Plane "L4_PLANE_IOVDD_P112" (solid, remove dead copper, pour order 112): 1350,1984.54 1350,1163 1391.5,1163 1802.5,752 1824,752 1824,1984.54
AVDD on L4_Plane "L4_PLANE_AVDD_P039" (solid, remove dead copper, pour order 39): 20,2153.37 400.14,2152.02 1054,2152.02 1054,2101.46 1110,2101.46 1110,1511 1253.72,1511 1254,1155 1383,1155 1820.32,717.68 886,717.68 886,0 20,0
IOVDD on L4_Plane "L4_PLANE_IOVDD_P043" (solid, remove dead copper, pour order 43): 1495.91,1984.2 1123.76,1984.2 1123.76,1524.08 1255.22,1524.08 1255.22,1459.65 1255.22,1159.78 1358.94,1161.2 1363.6,1984.2 1824.36,1984.2 1824.36,2149.75 1495.91,2149.79
GND on L5_GND2 "L5_GND2_GND_P120" (solid, remove dead copper, pour order 120): 20,2730 1120,2730 3980,2730 3980,20 1834.59,20 20,20
NetC27_1 on L6_Bottom Layer "L6_BOTTOM_LAYER_NETC27_1_P142" (solid, remove dead copper, pour order 142): 2180,977.1 2180,462 2291.03,462 2291.03,552 2259,552 2259,806.31 2315.65,896 2457,896 2457,977.1
-0.23V_CHB on L6_Bottom Layer "L6_BOTTOM_LAYER_-0.23V_CHB_P138" (solid, remove dead copper, pour order 138): 1101.8,2161.5 1101.8,2279 919.5,2279 919.5,2161.5
VS+_CHB on L6_Bottom Layer "L6_BOTTOM_LAYER_VS+_CHB_P136" (solid, remove dead copper, pour order 136): 1309.32,2162 1309.32,2280.5 1189.32,2280.5 1189.32,2162
-0.23V_CHA on L6_Bottom Layer "L6_BOTTOM_LAYER_-0.23V_CHA_P128" (solid, pour order 128): 1743.87,563 1743.87,482 1191.32,482 1191.32,563
VS+_CHA on L6_Bottom Layer "L6_BOTTOM_LAYER_VS+_CHA_P126" (solid, remove dead copper, pour order 126): 993.32,587.74 993.32,458.74 1113.32,458.74 1113.32,587.74

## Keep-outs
Keep-Out Layer:
  text ".Layer_Name" at 577,-1885.49 h60

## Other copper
L1_Top Layer:
  rectangle net NetC24_2: 932.44,1353.65 946.44,1365.65
  rectangle net GND: 992.44,1352.65 1004.44,1365.65
  region net VREF: 1097,1426.79 1092.21,1426.79 1082,1437 1035,1437 1035,1452.44 1084.57,1452.44 1084.57,1441.43 1092.4,1433.6 1097,1433.6
  text ".Layer_Name" at 577,-1885.49 h60
L2_GND1:
  pour cut-out: 913.76,1567.3 930.26,1567.3 952.24,1567.3 952.24,1585 913.76,1585
  pour cut-out: 1481.75,2517.66 1481.75,2735 1574.25,2735 1574.25,2517.66
  pour cut-out: 707.25,2515.66 707.25,2733 805.25,2733 805.25,2515.66
  pour cut-out: 1216.64,1675 1216.64,1779 1285.36,1779 1285.36,1675.02 1285.39,1675
  pour cut-out: 1016,1675 1016,1779 1084.73,1779 1084.73,1675.02 1084.75,1675
  pour cut-out: 1217.3,2036.5 1217.3,2140.5 1286.02,2140.5 1286.02,2036.53 1286.04,2036.5
  pour cut-out: 1216.07,1876.48 1216.07,1980.48 1284.8,1980.48 1284.8,1876.5 1284.82,1876.48
  pour cut-out: 1116.05,1876.5 1116.05,1980.5 1184.77,1980.5 1184.77,1876.53 1184.8,1876.5
  pour cut-out: 1117.3,2036.5 1117.3,2140.5 1186.02,2140.5 1186.02,2036.53 1186.04,2036.5
  pour cut-out: 1017.3,2036.5 1017.3,2140.5 1086.02,2140.5 1086.02,2036.53 1086.04,2036.5
  pour cut-out: 1016.3,1876.5 1016.3,1980.5 1085.02,1980.5 1085.02,1876.53 1085.04,1876.5
  pour cut-out: 1016.64,2240 1016.64,2344 1085.36,2344 1085.36,2240.02 1085.39,2240
  pour cut-out: 977.75,1589 994.25,1589 994.25,1607.5 977.75,1607.5
  pour cut-out: 934,1684 934,1664 972,1664 972,1684
  pour cut-out: 960.52,1544.3 977.02,1544.3 977.02,1565.5 999,1565.5 999,1608.5 960.52,1608.5
  pour cut-out: 1219,458.64 1219,563 1288.54,563 1288.54,458.64
  pour cut-out: 1019.5,659 1019.5,763 1088.23,763 1088.23,659.02 1088.25,659
  pour cut-out: 1019.5,781 1019.5,885 1088.23,885 1088.23,781.02 1088.25,781
  pour cut-out: 1119.5,781 1119.5,885 1188.23,885 1188.23,781.02 1188.25,781
  pour cut-out: 1119.25,659 1119.25,763 1187.98,763 1187.98,659.02 1188,659
  pour cut-out: 1219.27,658.98 1219.27,762.98 1288,762.98 1288,659 1288.02,658.98
  pour cut-out: 1219.5,781 1219.5,885 1288.23,885 1288.23,781.02 1288.25,781
  pour cut-out: 1219.5,980 1219.5,1085 1288.23,1085 1288.23,980.02
  pour cut-out: 1018.73,979.99 1018.73,1085 1088.23,1085 1088.23,980.01
  pour cut-out: 575.99,1294.36 683.12,1294.36 683.12,1225.64 576.01,1225.64
  pour cut-out: 575.99,1495.36 683.13,1495.36 683.13,1426.64 576.01,1426.64
  pour cut-out: 376,1294 483,1294 483,1225.27 376.02,1225.27
  pour cut-out: 1480.5,21 1480.5,233 1575,233 1575,21
  pour cut-out: 731,21 731,233.5 825,233.5 825,21
  pour cut-out: 13,1780.25 234,1780.25 234,1687.75 13,1687.75
  pour cut-out: 5,1031.25 238,1031.25 238,938.75 5,938.75
L6_Bottom Layer:
  text ".Layer_Name" at 577,-1885.49 h60
Multi-Layer:
  pour cut-out: 0,0 400,0 400,300 300,400 401,400 0,400
  pour cut-out: 0,2750 0,2350 300,2350 400,2450 400,2349 400,2750

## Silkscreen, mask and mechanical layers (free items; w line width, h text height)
Top Overlay:
  text "5V_EXT" at 2093,2531 h60
  text "-0.23V_B" at 582,2301 h40
  text "+3.3VB" at 1361,2102 h60
  text "VREF" at 739,1835 h60
  text "GND" at 439,1730.5 h60
  text "IOVDD" at 1578,1589 h60
  text "DC134" at 3076,1329.5 h72.83
  text "REV E" at 3076,1252.5 h72.83
  text "PLL LOCK" at 2112,1095 h72.83
  text "VCM" at 817.5,1066 h60
  text "GND" at 597,1032 h30
  text "GND" at 350,1026.5 h30
  text "PDN/" at 350,952 h30
  text "REFBUF" at 550.5,927.5 h30
  text "SYNC" at 350,910 h30
  text "GND" at 1492.33,894 h60
  text "CDC 3.3V" at 1896.74,828 h60
  text "AVDD" at 347.5,815.5 h30
  text "AVDD" at 573,815.5 h30
  text "+3.3VA" at 781,641.5 h60
  text "AVDD" at 599,549 h60
  text "-0.23V_A" at 1455,505 h60
  text "GND" at 90,502 h60
  text "DCLKIN" at 3064,122 h60
  text ".Layer_Name" at 577,-1885.49 h60
Bottom Overlay:
  lines w7: 273,1697 273,1771
  text ".Layer_Name" at 577,-1885.49 h60
Top Paste:
  text ".Layer_Name" at 577,-1885.49 h60
Bottom Paste:
  text ".Layer_Name" at 577,-1885.49 h60
Top Solder:
  text ".Layer_Name" at 577,-1885.49 h60
  text ".Layer_Name" at 577,-1885.49 h60
Bottom Solder:
  text ".Layer_Name" at 577,-1885.49 h60
Drill Guide:
  text ".Layer_Name" at 577,-1885.49 h60
M1 Board Outline:
  the board outline again, w7
  text ".Layer_Name" at 577,-1885.49 h60
M2 Board Dimensions:
  rectangle: 0,-1302 125,-1177
  rectangle: 125,-1427 500,-1302
  lines w7: 0,-1302 1000,-1302 ; 125,-1427 125,-1177 ; 250,-1427 250,-1177 ; 500,-1427 500,-1177 ; 750,-1427 750,-1177 ; 0,-1427 1000,-1427 1000,-1177 0,-1177 0,-1427
  text ".Layer_Name" at 577,-1885.49 h60
M3 3D STEP Top:
  text ".Layer_Name" at 577,-1885.49 h60
M4 3D STEP Bottom:
  text ".Layer_Name" at 577,-1885.49 h60
M5 Assembly Top:
  lines w10: -292,-1957.17 6308,-1957.17 ; -292,-1753.83 6310,-1753.83 ; -292,-1550.5 -292,-2160.5 3713,-2160.5 6310,-2160.5 6310,-1550.5 -291.5,-1550.5 -291.5,-2160.5 1284,-2160.5 ; 2173,-2160.5 2173,-1550.5 ; 3440,-1753.83 3440,-1550.5 ; 4280,-1753.83 4280,-1550.5 ; 4902,-2167 4902,-1964.17
  text "COMPONENTS MARKED 'DNP' SHOULD NOT BE POPULATED." at 1153.5,-1345.5 h60
  text "ASSEMBLY VARIANT:" at 1153,-1461 h60
  text ".VariantName" at 2189,-1461 h60
  text "PCB VIEWED FROM TOP SIDE" at -228.5,-1682.67 h60
  text "BOARD #:" at 2248,-1682.67 h60
  text ".PRJ_Number" at 2793.5,-1682.67 h60
  text "REV:" at 3638,-1682.67 h60
  text ".PCB_Rev" at 3929.5,-1682.67 h60
  text "SVN REV:" at 4476,-1682.67 h60
  text ".VersionControl_RevNumber" at 4982,-1682.67 h60
  text "TID #:" at 2248,-1886 h60
  text ".TID" at 2793.5,-1886 h60
  text "PLOT NAME =" at -228.5,-2091.34 h60
  text ".plot_File_Name" at 577,-2091.34 h60
  text "GENERATED    :" at 2250,-2091.34 h60
  text ".Print_Date" at 3119.5,-2091.34 h60
  text ".Print_Time" at 3848.5,-2091.34 h60
  text "TEXAS INSTRUMENTS" at 5113,-2091.34 h60
M6 Assembly Bottom:
  lines w10: -292.5,-1754.33 6309.5,-1754.33 ; -290.5,-1957.67 6309.5,-1957.67 ; 1115.5,-2167.5 1115.5,-1964.67 ; 1737.5,-1754.33 1737.5,-1551 ; 2577.5,-1754.33 2577.5,-1551 ; 3844.5,-2161 3844.5,-1551 ; 4733.5,-2161 6309,-2161 6309,-1551 -292.5,-1551 -292.5,-2161 2304.5,-2161 6309.5,-2161 6309.5,-1551
  text "COMPONENTS MARKED 'DNP' SHOULD NOT BE POPULATED." at 6102,-1345 h60
  text ".VariantName" at 5058,-1461 h60
  text "ASSEMBLY VARIANT:" at 6097,-1461 h60
  text ".VersionControl_RevNumber" at 1035.5,-1683.17 h60
  text "SVN REV:" at 1541.5,-1683.17 h60
  text ".PCB_Rev" at 2088,-1683.17 h60
  text "REV:" at 2379.5,-1683.17 h60
  text ".PRJ_Number" at 3224,-1683.17 h60
  text "BOARD #:" at 3769.5,-1683.17 h60
  text "PCB VIEWED FROM BOTTOM SIDE" at 6246,-1683.17 h60
  text ".TID" at 3224,-1886.5 h60
  text "TID #:" at 3769.5,-1886.5 h60
  text "TEXAS INSTRUMENTS" at 904.5,-2091.84 h60
  text ".Print_Time" at 2169,-2091.84 h60
  text ".Print_Date" at 2898,-2091.84 h60
  text "GENERATED    :" at 3767.5,-2091.84 h60
  text ".plot_File_Name" at 5440.5,-2091.84 h60
  text "PLOT NAME =" at 6246,-2091.84 h60
M9 Title Sheet:
  drawing of 57 lines, arcs and shapes, not listed
  text "1" at 739.84,7009.5 h70
  text "2" at 3235.5,7009.5 h70
  text "3" at 5724.84,7009.5 h70
  text "4" at 8231.51,7009.5 h70
  text "5" at 10730.5,7009.5 h70
  text "6" at 13235.5,7009.5 h70
  text "A" at -416.5,5866.5 h70
  text "A" at 14383.5,5866.5 h70
  text "B" at -416.5,3486.5 h70
  text "B" at 14383.5,3486.5 h70
  text "C" at -416.5,1111.5 h70
  text "C" at 14383.5,1111.5 h70
  text "PROJECT TITLE:" at 11343.5,-749.5 h45
  text "ADC3683EVM" at 11393.5,-882.83 h70
  text "DESIGNED FOR:" at 11343.5,-1050.5 h45
  text ".PRJ_Customer" at 11393.5,-1190.5 h70
  text "D" at -416.5,-1258.5 h70
  text "D" at 14383.5,-1258.5 h70
  text "FILE NAME:" at 11343.5,-1350.5 h45
  text ".PCB_File_Name_No_Path" at 11393.5,-1470.5 h70
  text "Texas Instruments (TI) and/or its licensors do not warrant the accuracy or completeness of this specification" at 6374,-1632.34 h45
  text "ENGINEER:" at 11343.5,-1640.5 h45
  text "LAYOUT BY:" at 12848.5,-1640.5 h45
  text "or any information contained therein. TI and/or its licensors do not warrant that this design will meet" at 6329.01,-1745 h45
  text "Daniel Brock" at 11393.5,-1795.49 h70
  text "Daniel Brock" at 12899,-1795.49 h70
  text "the specifications, will be suitable for your application or fit for any particular purpose, or will operate in" at 6329.01,-1857.67 h45
  text ".Layer_Name" at 577,-1885.49 h60
  text "ALTIUM DESIGNER VERSION:" at 12848.5,-1950.5 h45
  text "an implementation. TI and/or its licensors do not warrant that the design is production worthy. You should" at 6329.01,-1970.33 h45
  text "completely validate and test your design implementation to confirm the system functionality for your application." at 6374,-2083 h45
  text ".print_Scale" at 11393.5,-2083.83 h70
  text ".Application_BuildNumber" at 12899,-2083.83 h70
  text "1" at 739.84,-2290.5 h70
  text "2" at 3235.5,-2290.5 h70
  text "3" at 5724.84,-2290.5 h70
  text "4" at 8231.51,-2290.5 h70
  text "5" at 10730.5,-2290.5 h70
  text "6" at 13235.5,-2290.5 h70
M10 Fab Notes:
  drawing of 191 lines, arcs and shapes, not listed
  text "NOTE:" at -98,5482 h100
  text "DESIGN INFORMATION" at 12382.02,5329.17 h60
  text "1. 5 MIL DIFFERENTIAL PAIRS  ON  L1 AND  L3 LAYERS  ARE  100 OHMS  +/- 10%" at -50,5294 h70
  text "5" at 12781.5,5199.1 h60
  text "MIN. TRACK WIDTH:" at 11737.46,5197.05 h60
  text "MIL" at 12988.46,5197.05 h60
  text "2. ALL  VIA HOLES  NEED TO BE TENTED ON TOP AND BOTTOM SIDE." at -63,5164 h70
  text "MIN. CLEARANCE:" at 11737.46,5072.92 h60
  text "mil" at 12988.46,5072.92 h60
  text "5" at 12746.5,5068 h60
  text "3. VIA HOLES UNDER IC U2 NEED TO BE FILLED WITH SOLDER MASK TO PREVENT SOLDER PASTE FLOW INTO VIAS." at -69,5001 h70
  text "MIN. VIA PAD SIZE:" at 11737.46,4948.8 h60
  text "MIL" at 13064,4949.42 h60
  text "18" at 12766,4947 h60
  text "IPC Class 2 specifications" at 12432.46,4818.9 h60
  text "MINIMUM ANNULAR RING" at 11408.23,4810.67 h60
  text "PER" at 11608.23,4700.55 h60
  text "IPC-D-275 CLASS 2 LEVEL C" at 11828.23,4700.54 h60
  text "MIL, HOLES" at 13316.46,4600.07 h60
  text "+/-" at 12924,4591.48 h60
  text "+/-" at 13778,4591.48 h60
  text "REGISTRATION TOLERANCES:" at 11408.23,4590.42 h60
  text "METAL" at 12608,4590.42 h60
  text "5" at 13184.2,4590.42 h60
  text "3" at 14017.2,4590.42 h60
  text "MIL" at 14133.46,4590.42 h60
  text "HOLE SIZE TOLERANCE (UNLESS OTHERWISE SPECIFIED):" at 11408.23,4492.1 h60
  text "+/-" at 13778,4489.23 h60
  text "3" at 14017.2,4488.17 h60
  text "MIL" at 14133.46,4488.17 h60
  text "MATERIAL:" at 11333.46,4350.52 h60
  text "FR-4 High Tg" at 12319.9,4222 h60
  text "X" at 13068,4220 h60
  text "370HR" at 13586,4210 h60
  text "FR-408" at 11754.46,4209.49 h60
  text "OTHER" at 13242.46,4209.49 h60
  text "62 MIL +/-10%" at 12074.56,4066.46 h60
  text "X" at 11954.46,4064.01 h60
  text "THICKNESS:" at 11408.23,4058.24 h60
  text "OTHER" at 13359.46,4058.24 h60
  text "TOLERANCE:" at 11408.23,3919.92 h60
  text "X" at 12256.46,3919.92 h60
  text "ANSI IPC-6012 TYPE 3 CLASS 2" at 12434.48,3919.92 h60
  text "OTHER +/-" at 12434.46,3775.73 h60
  text "BOW & TWIST:" at 11408.23,3630.54 h60
  text "X" at 12256.46,3630.54 h60
  text "ANSI IPC-6012 TYPE 3 CLASS 2" at 12434.48,3630.54 h60
  text "OTHER +/-" at 12434.46,3483.85 h60
  text "DRILLING:" at 11333.46,3353.23 h60
  text "NC_DRILL FILES" at 13094.46,3248.04 h60
  text "REFERENCE:" at 11408.23,3244.1 h60
  text "X" at 12065.46,3244.01 h60
  text "AS SHOWN" at 12243.46,3244.1 h60
  text "X" at 12966.46,3244.1 h60
  text "OTHER" at 13392.46,3101.85 h60
  text "PTH COPPER THICKNESS:" at 11407.91,3098.32 h60
  text "X" at 12547.14,3098.32 h60
  text "20-30 um" at 12675.14,3098.32 h60
  text "BOARD FINISH:" at 11333.46,2950.73 h60
  text "SILKSCREEN:" at 11488.68,2840.6 h60
  text "X" at 12446.46,2840.6 h60
  text "TOP" at 12563.46,2840.6 h60
  text "X" at 12956.46,2840.6 h60
  text "BOTTOM" at 13074.46,2840.6 h60
  text "SILKSCREEN COLOR:" at 11488.68,2685.41 h60
  text "X" at 12445.46,2685.41 h60
  text "WHITE" at 12563.46,2685.41 h60
  text "OTHER" at 13074.46,2685.41 h60
  text "GREEN" at 12694.46,2541.96 h60
  text "X" at 13165.46,2541.96 h60
  text "OTHER" at 13312.46,2541.96 h60
  text "RED" at 13823.96,2541.96 h60
  text "SOLDER RESIST COLOR:" at 11488.68,2535.1 h60
  text "MATTE" at 12694.46,2387.71 h60
  text "X" at 13176.46,2387.71 h60
  text "SEMI-GLOSS" at 13312,2387.07 h60
  text "IMMERSION GOLD (ENIG)" at 12394.46,2214.94 h60
  text "ENEPIG" at 13732,2207.72 h60
  text "SURFACE FINISH:" at 11333.46,2206.72 h60
  text "X" at 13583.96,2204.41 h60
  text "IMM. TIN/SILVER OR EQUIV" at 11663,2069.4 h60
  text "OTHER" at 13094.46,2065.47 h60
  text "ARRAY/PANEL:" at 11333.46,1910.09 h60
  text "CUT AND TRIM PER M1 BOARD OUTLINE" at 12394.46,1901.87 h60
  text "X" at 12215,1899.13 h60
  text "N.C. ROUTE" at 12394.46,1765.9 h60
  text "V. SCORE" at 13260.46,1765.9 h60
  text "CERTIFICATION:" at 11333.46,1636.77 h60
  text "MATERIALS AND WORKMANSHIP FOR ALL PCBS" at 12058.46,1636.77 h60
  text "TO MEET OR EXCEED THE REQUIREMENTS OF:" at 12058.46,1542.71 h60
  text "X" at 11695.97,1414.08 h60
  text "ANSI IPC-A-600F CLASS ->" at 11823.96,1414.08 h60
  text "X" at 13471.97,1414.08 h60
  text "2" at 13581.96,1414.08 h60
  text "1" at 13266.96,1412.58 h60
  text "3" at 13935.96,1412.58 h60
  text "X" at 12507.97,1266.39 h60
  text "RoHS" at 12635.96,1266.39 h60
  text "OTHER" at 13280.36,1266.39 h60
  text "PER ORDER" at 13677.42,1266.39 h60
  text "ALL BOARDS MUST MEET OR EXCEED UL94-V0 REQUIREMENTS." at 11361,1112.57 h60
  text "PCB MUST BEAR THE UL94V-0 UL REGISTERED MATERIAL ID NUMBER" at 11361,996.5 h60
  text "ADDITIONAL REQUIREMENTS:" at 11333.46,827.08 h60
  text "MICROSECTION:" at 11408.23,719.95 h60
  text "YES" at 12313.96,719.95 h60
  text "REQUIRED" at 13175.46,575.62 h60
  text "BARE BOARD ELEC. TEST:" at 11408.23,572.76 h60
  text "NONE" at 12713.96,572.76 h60
  text "X" at 13057.46,572.76 h60
  text "PER ORDER" at 13767.46,572.76 h60
  text "XX MIL VIAS REQUIRE NON-CONDUCTIVE FILL AND PLANARIZE" at 11576.38,367.82 h59
  text "XX MIL VIAS REQUIRE CONDUCTIVE FILL AND PLANARIZE" at 11584.38,263.84 h60
  text "OUTER XX MIL TRACES REQUIRE 50 OHM SINGLE-ENDED IMPEDANCE" at 11583.39,100.46 h58
  text "LAYER 2 & 3 (INNER LAYERS) XX MIL WIDE, XX MIL SPACE / TRACES REQUIRE 100 OHM DIFFERENTIAL IMPEDANCE" at 11575.39,-135.26 h60
  text ".Layer_Name" at 577,-1885.49 h60
M11 Gerber Information:
  circle w5: c5611.87,719.23 r28.88
  circle w5: c5612.53,719.51 r50.07
  circle w5: c5809.66,723.28 r50.07
  circle w5: c5809,723 r28.88
  circle w5: c3966.66,-1277.72 r50.07
  circle w5: c3966,-1278 r28.88
  lines w4: 3891.65,-1278 3966,-1278 ; 3966,-1352.35 3966,-1278 ; 3966,-1203.65 3966,-1278 ; 4040.35,-1278 3966,-1278 ; 5537.52,719.23 5611.87,719.23 ; 5611.87,644.87 5611.87,719.23 ; 5611.87,793.58 5611.87,719.23 ; 5686.23,719.23 5611.87,719.23 ; 5734.65,723 5809,723 ; 5809,648.65 5809,723 ; 5809,797.35 5809,723 ; 5883.35,723 5809,723
  lines w10: -292,-1957.17 6308,-1957.17 ; -292,-1753.83 6310,-1753.83 ; -292,-1550.5 -292,-2160.5 3713,-2160.5 6310,-2160.5 6310,-1550.5 -291.5,-1550.5 -291.5,-2160.5 1284,-2160.5 ; 2173,-2160.5 2173,-1550.5 ; 3440,-1753.83 3440,-1550.5 ; 4280,-1753.83 4280,-1550.5 ; 4902,-2167 4902,-1964.17
  text "ALL ARTWORK VIEWED FROM TOP SIDE" at -228.5,-1682.67 h60
  text "BOARD #:" at 2248,-1682.67 h60
  text ".PRJ_Number" at 2793.5,-1682.67 h60
  text "REV:" at 3638,-1682.67 h60
  text ".PCB_Rev" at 3929.5,-1682.67 h60
  text "SVN REV:" at 4476,-1682.67 h60
  text ".VersionControl_RevNumber" at 4982,-1682.67 h60
  text "LAYER NAME =" at -228.5,-1885.49 h60
  text "TID #:" at 2248,-1886 h60
  text ".TID" at 2793.5,-1886 h60
  text "PLOT NAME =" at -228.5,-2091.34 h60
  text ".PRJ_Number" at 577,-2091.34 h60
  text "GENERATED    :" at 2250,-2091.34 h60
  text ".Print_Date" at 3119.5,-2091.34 h60
  text ".Print_Time" at 3848.5,-2091.34 h60
  text "TEXAS INSTRUMENTS" at 5113,-2091.34 h60
M12 Stackup:
  drawing of 399 lines, arcs and shapes, not listed
  text "Layer" at 5707.49,5289.1 h60
  text "Name" at 6117.4,5289.1 h60
  text "Material" at 7107.13,5289.1 h60
  text "Thickness" at 7966.89,5289.1 h60
  text "Constant" at 8616.73,5289.1 h60
  text "Board Layer Stack" at 9186.59,5289.1 h60
  text "1" at 5707.49,5169.1 h60
  text "Top Overlay" at 6117.4,5169.1 h60
  text "2" at 5707.49,5049.1 h60
  text "Top Solder" at 6117.4,5049.1 h60
  text "Solder Resist" at 7107.13,5049.1 h60
  text "0.50mil" at 7966.89,5049.1 h60
  text "3.5" at 8616.73,5049.1 h60
  text "3" at 5707.49,4929.1 h60
  text "L1_Top Layer" at 6117.4,4929.1 h60
  text "Copper" at 7107.13,4929.1 h60
  text "0.70mil" at 7966.89,4929.1 h60
  text "4" at 5707.49,4809.1 h60
  text "Dielectric 1" at 6117.4,4809.1 h60
  text "8.50mil" at 7966.89,4809.1 h60
  text "4.7" at 8616.73,4809.1 h60
  text "5" at 5707.49,4689.1 h60
  text "L2_GND1" at 6117.4,4689.1 h60
  text "Copper" at 7107.13,4689.1 h60
  text "0.70mil" at 7966.89,4689.1 h60
  text "6" at 5707.49,4569.1 h60
  text "Dielectric 2" at 6117.4,4569.1 h60
  text "14.00mil" at 7966.89,4569.1 h60
  text "4.7" at 8616.73,4569.1 h60
  text "7" at 5707.49,4449.1 h60
  text "L3_Signal" at 6117.4,4449.1 h60
  text "Copper" at 7107.13,4449.1 h60
  text "0.70mil" at 7966.89,4449.1 h60
  text "8" at 5707.49,4329.1 h60
  text "Dielectric 3" at 6117.4,4329.1 h60
  text "8.50mil" at 7966.89,4329.1 h60
  text "4.7" at 8616.73,4329.1 h60
  text "9" at 5707.49,4209.1 h60
  text "L4_Plane" at 6117.4,4209.1 h60
  text "Copper" at 7107.13,4209.1 h60
  text "0.70mil" at 7966.89,4209.1 h60
  text "10" at 5707.49,4089.1 h60
  text "Dielectric 4" at 6117.4,4089.1 h60
  text "14.00mil" at 7966.89,4089.1 h60
  text "4.7" at 8616.73,4089.1 h60
  text "11" at 5707.49,3969.1 h60
  text "L5_GND2" at 6117.4,3969.1 h60
  text "Copper" at 7107.13,3969.1 h60
  text "0.70mil" at 7966.89,3969.1 h60
  text "12" at 5707.49,3849.1 h60
  text "Dielectric 5" at 6117.4,3849.1 h60
  text "8.50mil" at 7966.89,3849.1 h60
  text "4.7" at 8616.73,3849.1 h60
  text "13" at 5707.49,3729.1 h60
  text "L6_Bottom Layer" at 6117.4,3729.1 h60
  text "Copper" at 7107.13,3729.1 h60
  text "0.70mil" at 7966.89,3729.1 h60
  text "14" at 5707.49,3609.1 h60
  text "Bottom Solder" at 6117.4,3609.1 h60
  text "Solder Resist" at 7107.13,3609.1 h60
  text "0.50mil" at 7966.89,3609.1 h60
  text "3.5" at 8616.73,3609.1 h60
  text "15" at 5707.49,3489.1 h60
  text "Bottom Overlay" at 6117.4,3489.1 h60
  text ".Layer_Name" at 577,-1885.49 h60
M13 Component Bodies Top:
  text ".Layer_Name" at 577,-1885.49 h60
M14 Component Bodies Bottom:
  text ".Layer_Name" at 577,-1885.49 h60
M15 Courtyards Top:
  text ".Layer_Name" at 577,-1885.49 h60
M16 Courtyards Bottom:
  text ".Layer_Name" at 577,-1885.49 h60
